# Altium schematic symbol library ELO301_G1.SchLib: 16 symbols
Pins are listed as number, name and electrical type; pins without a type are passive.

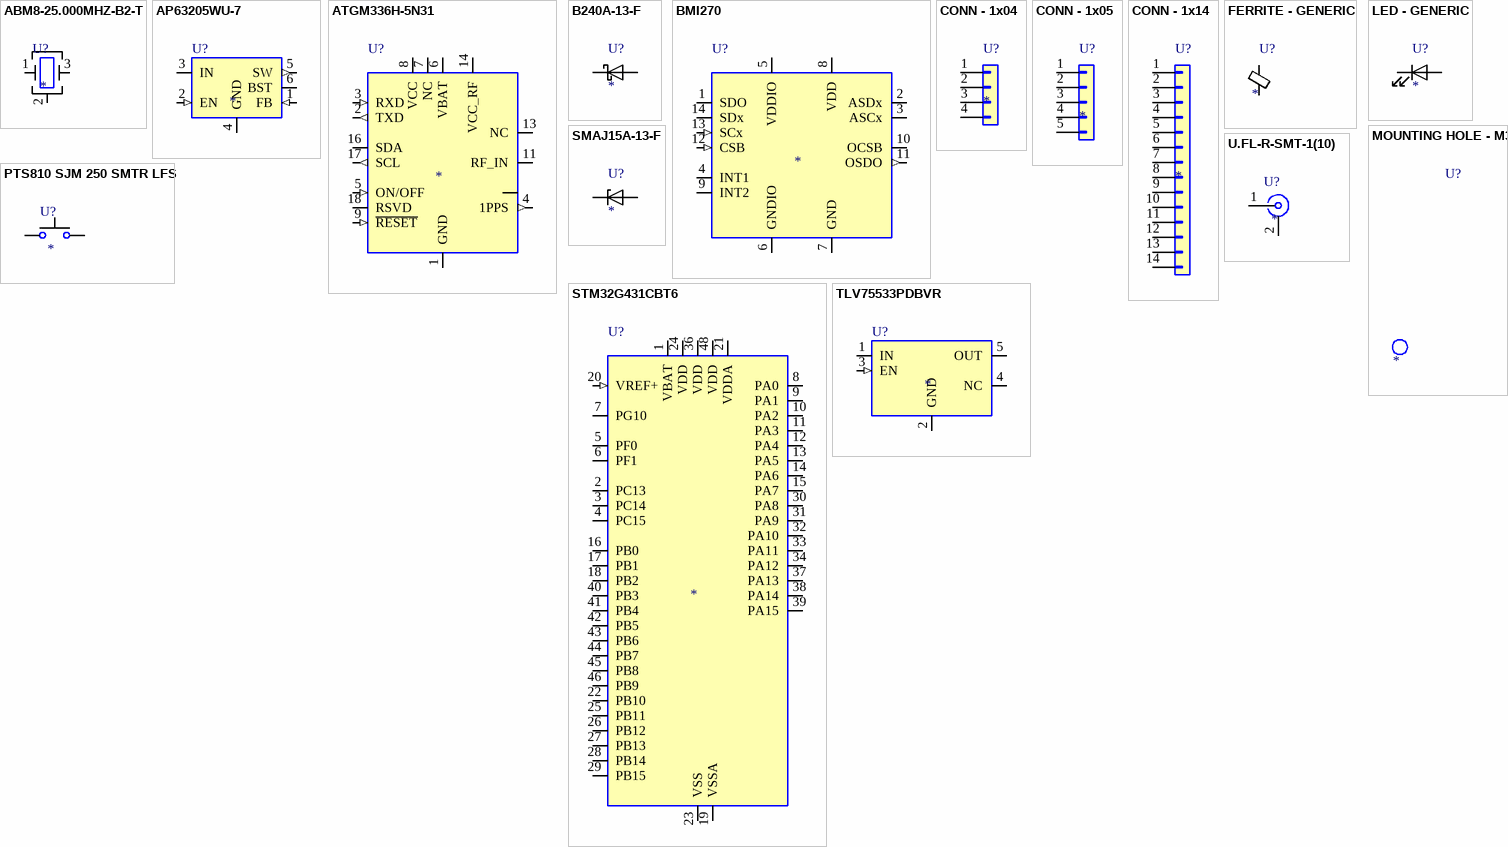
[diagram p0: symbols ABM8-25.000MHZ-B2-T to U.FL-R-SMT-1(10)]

## ABM8-25.000MHZ-B2-T
designator U?
Four pin crystal, GND on pins 2 and 4
pins: 1, 2 G, 3, 4 G

## AP63205WU-7
designator U?
2A, 1.1MHz Buck DC/DC Converter, fixed 5.0V output voltage, TSOT-23-6
pins: 1 FB (in), 2 EN (in), 3 IN (power), 4 GND (power), 5 SW (out), 6 BST

## ATGM336H-5N31
designator U?
ZKW ATGM336H-5N31 modulo GNSS GPS+BDS, UART + 1PPS, LCC-18 9.7x10.1mm (huella compatible u-blox MAX)
pins: 1 GND (power), 2 TXD (out), 3 RXD (in), 4 1PPS (out), 5 ON/OFF (in), 6 VBAT (power), 7 NC, 8 VCC (power), 9 ~{RESET} (in), 10 GND, 11 RF_IN, 12 GND, 13 NC, 14 VCC_RF (power), 15 RSVD, 16 SDA (io), 17 SCL (out), 18 RSVD

## B240A-13-F
designator U?
Schottky diode
pins: 1 K, 2 A

## BMI270
designator U?
Bosch BMI270 IMU 6 ejes (acelerometro + giroscopio), SPI/I2C, LGA-14 2.5x3.0mm
pins: 1 SDO (io), 2 ASDx (io), 3 ASCx (io), 4 INT1 (io), 5 VDDIO (power), 6 GNDIO (power), 7 GND (power), 8 VDD (power), 9 INT2 (io), 10 OCSB, 11 OSDO (out), 12 CSB (in), 13 SCx (in), 14 SDx (io)

## CONN - 1x04
designator U?
Generic connector, single row, 01x04, script generated (kicad-library-utils/schlib/autogen/connector/)
pins: 1 Pin_1, 2 Pin_2, 3 Pin_3, 4 Pin_4

## CONN - 1x05
designator U?
Generic connector, single row, 01x05, script generated (kicad-library-utils/schlib/autogen/connector/)
pins: 1 Pin_1, 2 Pin_2, 3 Pin_3, 4 Pin_4, 5 Pin_5

## CONN - 1x14
designator U?
Generic connector, single row, 01x14, script generated (kicad-library-utils/schlib/autogen/connector/)
pins: 1 Pin_1, 2 Pin_2, 3 Pin_3, 4 Pin_4, 5 Pin_5, 6 Pin_6, 7 Pin_7, 8 Pin_8, 9 Pin_9, 10 Pin_10, 11 Pin_11, 12 Pin_12, 13 Pin_13, 14 Pin_14

## FERRITE - GENERIC
designator U?
Ferrite bead, small symbol
pins: 1, 2

## LED - GENERIC
designator U?
Light emitting diode
pins: 1 K, 2 A

## MOUNTING HOLE - M3
designator U?
Mounting Hole without connection

## PTS810 SJM 250 SMTR LFS
designator U?
Push button switch, generic, two pins
pins: 1, 2

## SMAJ15A-13-F
designator U?
Diodes SMAJ15A TVS unidireccional 400 W, 15 V de trabajo, SMA
pins: 1 K, 2 A

## STM32G431CBT6
designator U?
STMicroelectronics Arm Cortex-M4 MCU, 128KB flash, 32KB RAM, 170 MHz, 1.71-3.6V, 38 GPIO, LQFP48
pins: 1 VBAT (power), 2 PC13 (io), 3 PC14 (io), 4 PC15 (io), 5 PF0 (io), 6 PF1 (io), 7 PG10 (io), 8 PA0 (io), 9 PA1 (io), 10 PA2 (io), 11 PA3 (io), 12 PA4 (io), 13 PA5 (io), 14 PA6 (io), 15 PA7 (io), 16 PB0 (io), 17 PB1 (io), 18 PB2 (io), 19 VSSA (power), 20 VREF+ (in), 21 VDDA (power), 22 PB10 (io), 23 VSS (power), 24 VDD (power), 25 PB11 (io), 26 PB12 (io), 27 PB13 (io), 28 PB14 (io), 29 PB15 (io), 30 PA8 (io), 31 PA9 (io), 32 PA10 (io), 33 PA11 (io), 34 PA12 (io), 35 VSS, 36 VDD (power), 37 PA13 (io), 38 PA14 (io), 39 PA15 (io), 40 PB3 (io), 41 PB4 (io), 42 PB5 (io), 43 PB6 (io), 44 PB7 (io), 45 PB8 (io), 46 PB9 (io), 47 VSS, 48 VDD (power)

## TLV75533PDBVR
designator U?
TI TLV75533 LDO 500 mA, salida fija 3,3 V, SOT-23-5
pins: 1 IN (power), 2 GND (power), 3 EN (in), 4 NC, 5 OUT (power)

## U.FL-R-SMT-1(10)
designator U?
coaxial connector (BNC, SMA, SMB, SMC, Cinch/RCA, LEMO, ...)
pins: 1 In, 2 Ext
